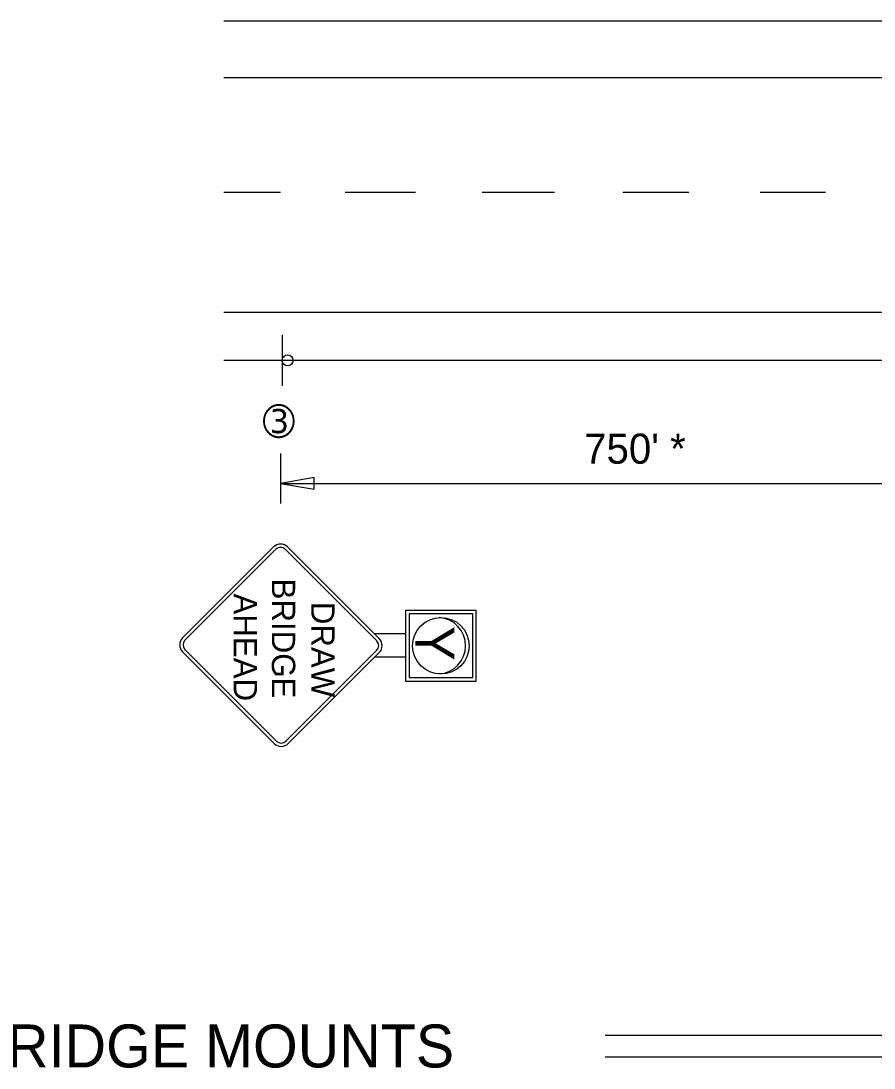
# Model space of a CAD drawing. Extents: x 15 to 764, y 7 to 487.
# Drawn here: x 378.2 to 477.5, y 310.1 to 432 of the extents above; entities that cross this region are included whole.
import ezdxf

# ---------------------------------------------------------------- set-up
doc = ezdxf.new("R2010")
doc.units = 0
for name, color, linetype in [('Default', 7, 'Continuous'), ('Dimension', 7, 'Continuous'), ('TextStructures', 7, 'Continuous')]:
    doc.layers.add(name, color=color, linetype=linetype)

msp = doc.modelspace()

# ---------------------------------------------------------------- linework, layer by layer
at = {"layer": 'Default'}
for p, q in [((401.85, 431.97), (746.65, 431.97)), ((401.85, 425.41), (746.65, 425.41)), ((401.85, 412.04), (408.42, 412.04)), ((415.94, 412.04), (424.15, 412.04)), ((431.9, 412.04), (440.32, 412.04)), ((448.26, 412.04), (455.94, 412.04)), ((464.22, 412.04), (471.81, 412.04)), ((401.85, 398.09), (746.65, 398.09)), ((408.63, 395.47), (408.63, 389.52)), ((408.63, 395.21), (408.63, 389.8)), ((401.85, 392.5), (746.65, 392.5)), ((408.43, 381.66), (408.43, 375.84)), ((408.43, 378.17), (494.33, 378.17)), ((397.05, 360.19), (407.63, 370.77)), ((397.32, 359.92), (407.91, 370.5)), ((408.98, 370.5), (419.64, 359.83)), ((409.26, 370.77), (419.92, 360.11)), ((422.98, 363.39), (422.98, 355.17)), ((431.2, 363.39), (422.98, 363.39)), ((431.2, 355.17), (431.2, 363.39)), ((423.39, 362.98), (423.39, 355.58)), ((430.79, 362.98), (423.39, 362.98)), ((430.79, 355.58), (430.79, 362.98)), ((412.7, 361.22), (412.7, 361.22)), ((419.34, 360.69), (422.97, 360.69)), ((397.05, 358.57), (407.71, 347.9)), ((397.32, 358.84), (407.98, 348.18)), ((409.06, 348.18), (419.64, 358.76)), ((409.33, 347.9), (419.92, 358.48)), ((419.41, 357.97), (422.97, 357.97)), ((422.98, 355.17), (431.2, 355.17)), ((423.39, 355.58), (430.79, 355.58))]:
    msp.add_line(p, q, dxfattribs=at)
for centre, radius in [((409.26, 392.49), 0.637), ((427.09, 359.28), 3.29)]:
    msp.add_circle(centre, radius, dxfattribs=at)
for centre, radius, start, end in [((408.45, 369.96), 1.15, 44.9847, 134.9857), ((408.45, 369.96), 0.762, 44.9847, 134.9857), ((426.68, 359.28), 3.29, 273.5833, 86.4167), ((397.86, 359.38), 1.15, 134.9857, 224.9846), ((397.86, 359.38), 0.762, 134.9857, 224.9846), ((419.1, 359.29), 0.762, 314.9852, 44.9843), ((419.1, 359.29), 1.15, 314.9852, 44.9843), ((408.52, 348.72), 1.15, 224.9848, 314.9852), ((408.52, 348.72), 0.762, 224.9848, 314.9852)]:
    msp.add_arc(centre, radius, start, end, dxfattribs=at)
at = {"layer": 'Dimension'}
msp.add_lwpolyline([(408.43, 378.17), (412.34, 377.51), (412.34, 378.84)], close=True, dxfattribs=at)
at = {"layer": 'TextStructures'}
for p, q in [((446.19, 313.96), (764.08, 313.96)), ((446.19, 311.46), (764.08, 311.46))]:
    msp.add_line(p, q, dxfattribs=at)

# ---------------------------------------------------------------- texts
at = {"layer": 'Default'}
for s, p in [('BRIDGE', (407.43, 367.09)), ('AHEAD', (402.99, 365.36)), ('DRAW', (412.01, 364.39))]:
    msp.add_text(s, height=2.718, rotation=270, dxfattribs=at).set_placement(p)
at = {"layer": 'TextStructures'}
msp.add_text('➂', height=3.5, dxfattribs=at).set_placement((406.39, 383.67))
for s, height, rotation, p in [("750' *", 3.5, 0.0007, (443.75, 380.46)), ('Y', 4.54, 270, (424.12, 361.58)), ('TYPICAL BRIDGE MOUNTS', 5, 0.0007, (342.45, 310.21))]:
    msp.add_text(s, height=height, rotation=rotation, dxfattribs=at).set_placement(p)

doc.saveas('drawing.dxf')
